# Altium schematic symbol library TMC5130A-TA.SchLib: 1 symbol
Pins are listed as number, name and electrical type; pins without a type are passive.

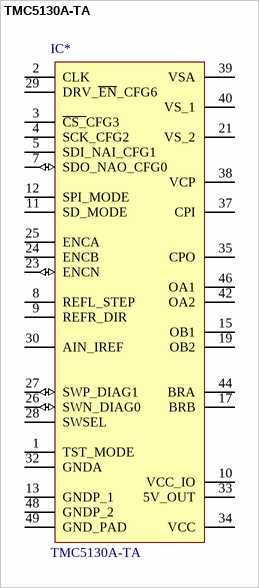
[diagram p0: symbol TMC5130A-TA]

## TMC5130A-TA
designator IC*
High voltage(up to 46V) controller for two-phase bipolar stepper motor, with SPI, Step/Dir, UART, TQFP48-EP(7x7); Manufacturer: TRINAMIC; Geometry.Height: 1,2mm; Ordercode - Distri#1: 1460-1124-ND
footprint TMC_TQFP48-EP_0.5_7.0X7.0
pins: 1 TST_MODE, 2 CLK, 3 ~{CS_}CFG3, 4 SCK_CFG2, 5 SDI_NAI_CFG1, 7 SDO_NAO_CFG0 (io), 8 REFL_STEP, 9 REFR_DIR, 10 VCC_IO (power), 11 SD_MODE, 12 SPI_MODE, 13 GNDP_1, 15 OB1, 17 BRB, 19 OB2, 21 VS_2 (power), 23 ENCN (io), 24 ENCB, 25 ENCA, 26 SWN_DIAG0 (io), 27 SWP_DIAG1 (io), 28 SWSEL, 29 DRV_~{EN}_CFG6, 30 AIN_IREF, 32 GNDA, 33 5V_OUT (power), 34 VCC (power), 35 CPO, 37 CPI, 38 VCP (power), 39 VSA (power), 40 VS_1 (power), 42 OA2, 44 BRA, 46 OA1, 48 GNDP_2, 49 GND_PAD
